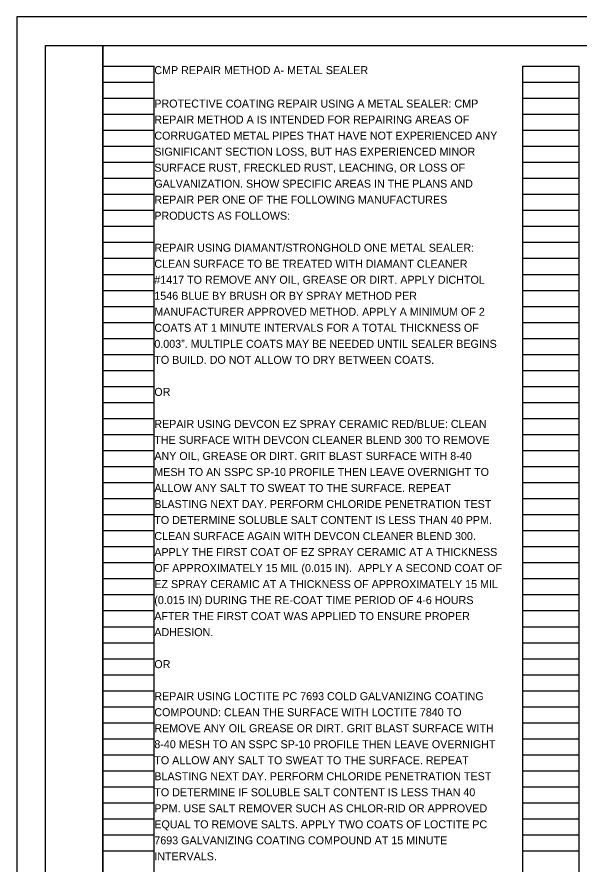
# Model space of a CAD drawing. Extents: x 0 to 42.3, y -7.4 to 22.
# Drawn here: x 0 to 9.82, y 7.19 to 22 of the extents above; entities that cross this region are included whole.
import ezdxf

# ---------------------------------------------------------------- set-up
doc = ezdxf.new("R2010")
doc.units = 0
for name, color, linetype in [('SH_Border', 7, 'Continuous'), ('SH_Cut_Line', 7, 'Continuous'), ('SH_Data', 7, 'Continuous'), ('SH_Text', 7, 'Continuous')]:
    doc.layers.add(name, color=color, linetype=linetype)

msp = doc.modelspace()

# ---------------------------------------------------------------- linework, layer by layer
at = {"layer": 'SH_Border'}
for points in [[(0.5, 21.5), (1.5, 21.5), (1.5, 0.5), (0.5, 0.5)], [(1.5, 21.5), (33.5, 21.5), (33.5, 0.5), (1.5, 0.5)]]:
    msp.add_lwpolyline(points, close=True, dxfattribs=at)
at = {"layer": 'SH_Cut_Line'}
msp.add_lwpolyline([(0, 0), (34, 0), (34, 22), (0, 22)], close=True, dxfattribs=at)
at = {"layer": 'SH_Data'}
for p, q in [((1.5, 0.98), (1.5, 21.14)), ((1.5, 21.14), (2.4, 21.14)), ((2.4, 0.98), (2.4, 21.14)), ((8.84, 0.98), (8.84, 21.14)), ((8.84, 21.14), (9.82, 21.14)), ((9.82, 0.98), (9.82, 21.14)), ((1.5, 20.86), (2.4, 20.86)), ((8.84, 20.86), (9.82, 20.86)), ((1.5, 20.58), (2.4, 20.58)), ((8.84, 20.58), (9.82, 20.58)), ((1.5, 20.3), (2.4, 20.3)), ((8.84, 20.3), (9.82, 20.3)), ((1.5, 20.02), (2.4, 20.02)), ((8.84, 20.02), (9.82, 20.02)), ((1.5, 19.74), (2.4, 19.74)), ((8.84, 19.74), (9.82, 19.74)), ((1.5, 19.46), (2.4, 19.46)), ((8.84, 19.46), (9.82, 19.46)), ((1.5, 19.18), (2.4, 19.18)), ((8.84, 19.18), (9.82, 19.18)), ((1.5, 18.9), (2.4, 18.9)), ((8.84, 18.9), (9.82, 18.9)), ((1.5, 18.62), (2.4, 18.62)), ((8.84, 18.62), (9.82, 18.62)), ((1.5, 18.34), (2.4, 18.34)), ((8.84, 18.34), (9.82, 18.34)), ((1.5, 18.06), (2.4, 18.06)), ((8.84, 18.06), (9.82, 18.06)), ((1.5, 17.78), (2.4, 17.78)), ((8.84, 17.78), (9.82, 17.78)), ((1.5, 17.5), (2.4, 17.5)), ((8.84, 17.5), (9.82, 17.5)), ((1.5, 17.22), (2.4, 17.22)), ((8.84, 17.22), (9.82, 17.22)), ((1.5, 16.94), (2.4, 16.94)), ((8.84, 16.94), (9.82, 16.94)), ((1.5, 16.66), (2.4, 16.66)), ((8.84, 16.66), (9.82, 16.66)), ((1.5, 16.38), (2.4, 16.38)), ((8.84, 16.38), (9.82, 16.38)), ((1.5, 16.1), (2.4, 16.1)), ((8.84, 16.1), (9.82, 16.1)), ((1.5, 15.82), (2.4, 15.82)), ((8.84, 15.82), (9.82, 15.82)), ((1.5, 15.54), (2.4, 15.54)), ((8.84, 15.54), (9.82, 15.54)), ((1.5, 15.26), (2.4, 15.26)), ((8.84, 15.26), (9.82, 15.26)), ((1.5, 14.98), (2.4, 14.98)), ((8.84, 14.98), (9.82, 14.98)), ((1.5, 14.7), (2.4, 14.7)), ((8.84, 14.7), (9.82, 14.7)), ((1.5, 14.42), (2.4, 14.42)), ((8.84, 14.42), (9.82, 14.42)), ((1.5, 14.14), (2.4, 14.14)), ((8.84, 14.14), (9.82, 14.14)), ((1.5, 13.86), (2.4, 13.86)), ((8.84, 13.86), (9.82, 13.86)), ((1.5, 13.58), (2.4, 13.58)), ((8.84, 13.58), (9.82, 13.58)), ((1.5, 13.3), (2.4, 13.3)), ((8.84, 13.3), (9.82, 13.3)), ((1.5, 13.02), (2.4, 13.02)), ((8.84, 13.02), (9.82, 13.02)), ((1.5, 12.74), (2.4, 12.74)), ((8.84, 12.74), (9.82, 12.74)), ((1.5, 12.46), (2.4, 12.46)), ((8.84, 12.46), (9.82, 12.46)), ((1.5, 12.18), (2.4, 12.18)), ((8.84, 12.18), (9.82, 12.18)), ((1.5, 11.9), (2.4, 11.9)), ((8.84, 11.9), (9.82, 11.9)), ((1.5, 11.62), (2.4, 11.62)), ((8.84, 11.62), (9.82, 11.62)), ((1.5, 11.34), (2.4, 11.34)), ((8.84, 11.34), (9.82, 11.34)), ((1.5, 11.06), (2.4, 11.06)), ((8.84, 11.06), (9.82, 11.06)), ((1.5, 10.78), (2.4, 10.78)), ((8.84, 10.78), (9.82, 10.78)), ((1.5, 10.5), (2.4, 10.5)), ((8.84, 10.5), (9.82, 10.5)), ((1.5, 10.22), (2.4, 10.22)), ((8.84, 10.22), (9.82, 10.22)), ((1.5, 9.94), (2.4, 9.94)), ((8.84, 9.94), (9.82, 9.94)), ((1.5, 9.66), (2.4, 9.66)), ((8.84, 9.66), (9.82, 9.66)), ((1.5, 9.38), (2.4, 9.38)), ((8.84, 9.38), (9.82, 9.38)), ((1.5, 9.1), (2.4, 9.1)), ((8.84, 9.1), (9.82, 9.1)), ((1.5, 8.82), (2.4, 8.82)), ((8.84, 8.82), (9.82, 8.82)), ((1.5, 8.54), (2.4, 8.54)), ((8.84, 8.54), (9.82, 8.54)), ((1.5, 8.26), (2.4, 8.26)), ((8.84, 8.26), (9.82, 8.26)), ((1.5, 7.98), (2.4, 7.98)), ((8.84, 7.98), (9.82, 7.98)), ((1.5, 7.7), (2.4, 7.7)), ((8.84, 7.7), (9.82, 7.7)), ((1.5, 7.42), (2.4, 7.42)), ((8.84, 7.42), (9.82, 7.42))]:
    msp.add_line(p, q, dxfattribs=at)

# ---------------------------------------------------------------- texts
at = {"layer": 'SH_Text'}
for s, p in [('CMP REPAIR METHOD A- METAL SEALER', (2.4, 21)), ('PROTECTIVE COATING REPAIR USING A METAL SEALER: CMP ', (2.4, 20.415)), ('REPAIR METHOD A IS INTENDED FOR REPAIRING AREAS OF ', (2.4, 20.135)), ('CORRUGATED METAL PIPES THAT HAVE NOT EXPERIENCED ANY ', (2.4, 19.855)), ('SIGNIFICANT SECTION LOSS, BUT HAS EXPERIENCED MINOR ', (2.4, 19.575)), ('SURFACE RUST, FRECKLED RUST, LEACHING, OR LOSS OF ', (2.4, 19.295)), ('GALVANIZATION. SHOW SPECIFIC AREAS IN THE PLANS AND ', (2.4, 19.015)), ('REPAIR PER ONE OF THE FOLLOWING MANUFACTURES ', (2.4, 18.735)), ('PRODUCTS AS FOLLOWS:', (2.4, 18.455)), ('REPAIR USING DIAMANT/STRONGHOLD ONE METAL SEALER: ', (2.4, 17.895)), ('CLEAN SURFACE TO BE TREATED WITH DIAMANT CLEANER ', (2.4, 17.615)), ('#1417 TO REMOVE ANY OIL, GREASE OR DIRT. APPLY DICHTOL ', (2.4, 17.335)), ('1546 BLUE BY BRUSH OR BY SPRAY METHOD PER ', (2.4, 17.055)), ('MANUFACTURER APPROVED METHOD. APPLY A MINIMUM OF 2 ', (2.4, 16.775)), ('COATS AT 1 MINUTE INTERVALS FOR A TOTAL THICKNESS OF ', (2.4, 16.495)), ('0.003”. MULTIPLE COATS MAY BE NEEDED UNTIL SEALER BEGINS ', (2.4, 16.215)), ('TO BUILD. DO NOT ALLOW TO DRY BETWEEN COATS. ', (2.4, 15.935)), ('OR', (2.4, 15.375)), ('REPAIR USING DEVCON EZ SPRAY CERAMIC RED/BLUE: CLEAN ', (2.4, 14.815)), ('THE SURFACE WITH DEVCON CLEANER BLEND 300 TO REMOVE ', (2.4, 14.535)), ('ANY OIL, GREASE OR DIRT. GRIT BLAST SURFACE WITH 8-40 ', (2.4, 14.255)), ('MESH TO AN SSPC SP-10 PROFILE THEN LEAVE OVERNIGHT TO ', (2.4, 13.975)), ('ALLOW ANY SALT TO SWEAT TO THE SURFACE. REPEAT ', (2.4, 13.695)), ('BLASTING NEXT DAY. PERFORM CHLORIDE PENETRATION TEST ', (2.4, 13.415)), ('TO DETERMINE SOLUBLE SALT CONTENT IS LESS THAN 40 PPM.', (2.4, 13.135)), ('CLEAN SURFACE AGAIN WITH DEVCON CLEANER BLEND 300.\xa0', (2.4, 12.855)), ('APPLY THE FIRST COAT OF\xa0EZ SPRAY CERAMIC AT A THICKNESS ', (2.4, 12.575)), ('OF APPROXIMATELY 15 MIL (0.015 IN). \xa0APPLY A SECOND COAT OF ', (2.4, 12.295)), ('EZ SPRAY CERAMIC AT A THICKNESS OF APPROXIMATELY 15 MIL ', (2.4, 12.015)), ('(0.015 IN) DURING THE\xa0RE-COAT\xa0TIME PERIOD OF 4-6 HOURS ', (2.4, 11.735)), ('AFTER THE FIRST COAT WAS APPLIED TO ENSURE PROPER ', (2.4, 11.455)), ('ADHESION.', (2.4, 11.175)), ('OR ', (2.4, 10.615)), ('REPAIR USING LOCTITE PC 7693 COLD GALVANIZING COATING ', (2.4, 10.055)), ('COMPOUND: CLEAN THE SURFACE WITH LOCTITE 7840 TO ', (2.4, 9.775)), ('REMOVE ANY OIL GREASE OR DIRT. GRIT BLAST SURFACE WITH ', (2.4, 9.495)), ('8-40 MESH TO AN SSPC SP-10 PROFILE THEN LEAVE OVERNIGHT ', (2.4, 9.215)), ('TO ALLOW ANY SALT TO SWEAT TO THE SURFACE. REPEAT ', (2.4, 8.935)), ('BLASTING NEXT DAY. PERFORM CHLORIDE PENETRATION TEST ', (2.4, 8.655)), ('TO DETERMINE IF SOLUBLE SALT CONTENT IS LESS THAN 40 ', (2.4, 8.375)), ('PPM. USE SALT REMOVER SUCH AS CHLOR-RID OR APPROVED ', (2.4, 8.095)), ('EQUAL TO REMOVE SALTS. APPLY TWO COATS OF LOCTITE PC ', (2.4, 7.815)), ('7693 GALVANIZING COATING COMPOUND AT 15 MINUTE ', (2.4, 7.535)), ('INTERVALS. ', (2.4, 7.255))]:
    msp.add_text(s, height=0.14, dxfattribs=at).set_placement(p)

doc.saveas('drawing.dxf')
